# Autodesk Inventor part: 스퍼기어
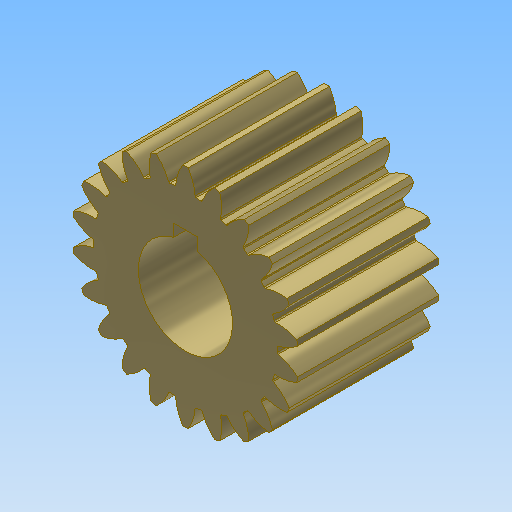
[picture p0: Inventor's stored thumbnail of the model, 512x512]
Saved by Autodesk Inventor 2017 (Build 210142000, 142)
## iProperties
Created: 2023-11
Part Number: 스퍼기어
Material: 알루미늄 6061
Document SubType Name: Modeling
Designer: mdu-01
Density: 1 g/cm^3
Appearance: 알루미늄 - 평지(1)
Author: mdu-01
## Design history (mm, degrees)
sketch "스케치1" dims "d2" = 44, "d5" = 2.5
  geometry: L1 (-2.5, 9.682)-(2.5, 9.682); L2 (2.5, 9.682)-(2.5, 12.3); L3 (2.5, 12.3)-(-2.5, 12.3); L4 (-2.5, 12.3)-(-2.5, 9.682); L5 (0, 0)-(0, 9.682); A1 r 10 centre (0, 0) between (-2.5, 9.682) and (2.5, 9.682); A2 r 24 centre (0, 0) between (0.57, 23.993) and (-0.57, 23.993); A3 r 9.393 centre (-7.31, 18.88) between (2.07, 19.39) and (0.57, 23.993); A4 r 9.393 centre (7.31, 18.88) between (-0.57, 23.993) and (-2.07, 19.39); A5 r 19.5 centre (0, 0) between (2.07, 19.39) and (-2.07, 19.39); 2 further points
  constraints: 11 point on circle, 10 end point, 5 centre point, 3 coincident, 3 symmetric about line, 2 parallel, 1 horizontal, 1 midpoint, 1 perpendicular, 7 other
  dimensions: "d0" = 20 diameter of A1; "d3" = 5 distance between parallel lines of L2 L4; "d4" = 2.3 distance edge to line of A1 L3; "d6" = 2 dimension on A2; "d7" = 1.57 horizontal distance of point (1.57, 21.944) L5.start; "d8" = 1 horizontal distance of A2.start point (1.57, 21.944); "d9" = 0.5 horizontal distance of point (1.57, 21.944) A3.start
extrude "돌출1" new body sketch "스케치1" distance "d10" = 30; taper "d11" = 0 deg
extrude "돌출2" join sketch "스케치1" distance "d12" = 30; taper "d13" = 0 deg
fillet "모깎기1" dims "d14" = 0.25
node "솔리드1"
pattern_circular "원형 패턴1" dims angle "d16" = 360 deg
